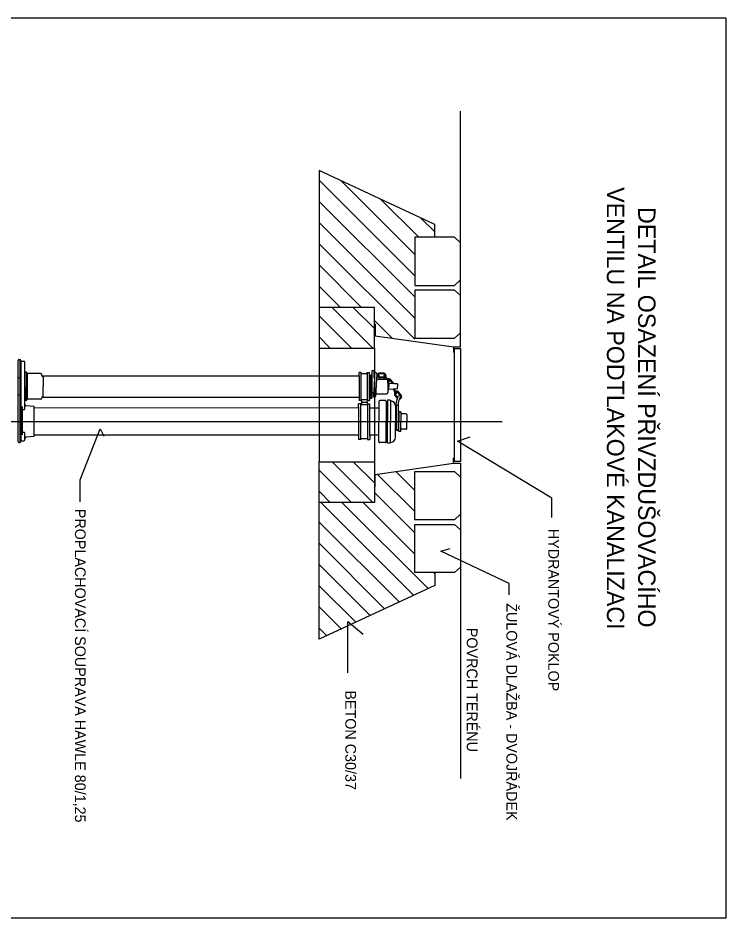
# Model space of a CAD drawing. Extents: x -548894.87 to -548891.9, y -1151272.48 to -1151270.38.
# Drawn here: x -548893.547 to -548891.896, y -1151272.484 to -1151270.384 of the extents above; entities that cross this region are included whole.
import ezdxf

# ---------------------------------------------------------------- set-up
doc = ezdxf.new("R2010")
doc.units = 0
doc.layers.add('Implicitní', color=7, linetype='Continuous')
doc.layers.add('Vrstva 2', color=7, linetype='Continuous')

msp = doc.modelspace()

# ---------------------------------------------------------------- linework, layer by layer
at = {"layer": 'Implicitní'}
for p, q in [((-548893.5465, -1151271.2988), (-548893.5465, -1151271.1823)), ((-548893.545, -1151271.1808), (-548893.5425, -1151271.1808)), ((-548893.5402, -1151271.1848), (-548893.5425, -1151271.1808)), ((-548893.5425, -1151271.3258), (-548893.5425, -1151271.1808)), ((-548893.5402, -1151271.1848), (-548893.5335, -1151271.1848)), ((-548893.5402, -1151271.3258), (-548893.5402, -1151271.1848)), ((-548893.5315, -1151271.285), (-548893.5315, -1151271.1868)), ((-548893.5275, -1151271.2108), (-548893.5315, -1151271.2108)), ((-548893.5315, -1151271.2438), (-548893.5315, -1151271.2108)), ((-548893.5275, -1151271.2768), (-548893.5275, -1151271.2108)), ((-548893.5275, -1151271.2108), (-548893.5257, -1151271.2138)), ((-548893.5257, -1151271.2138), (-548893.5257, -1151271.2738)), ((-548893.4945, -1151271.2138), (-548893.5257, -1151271.2138)), ((-548893.4915, -1151271.2173), (-548893.4915, -1151271.2168)), ((-548893.4887, -1151271.2188), (-548893.4069, -1151271.2188)), ((-548893.4887, -1151271.2188), (-548893.4887, -1151271.2438)), ((-548893.4069, -1151271.2188), (-548892.7516, -1151271.2188)), ((-548892.7466, -1151271.2113), (-548892.7516, -1151271.2113)), ((-548892.7516, -1151271.2188), (-548892.7516, -1151271.2113)), ((-548892.7516, -1151271.2188), (-548892.7516, -1151271.2763)), ((-548892.7466, -1151271.2743), (-548892.7466, -1151271.2113)), ((-548892.7466, -1151271.2133), (-548892.7326, -1151271.2133)), ((-548892.7326, -1151271.2133), (-548892.7326, -1151271.2113)), ((-548892.7326, -1151271.2113), (-548892.7276, -1151271.2113)), ((-548892.7326, -1151271.2133), (-548892.7326, -1151271.2763)), ((-548892.7276, -1151271.2763), (-548892.7276, -1151271.2113)), ((-548892.7276, -1151271.2188), (-548892.7246, -1151271.2188)), ((-548892.7246, -1151271.2668), (-548892.7246, -1151271.2168)), ((-548892.7246, -1151271.2168), (-548892.7216, -1151271.2168)), ((-548892.7216, -1151271.258), (-548892.7216, -1151271.2168)), ((-548892.7211, -1151271.2063), (-548892.7176, -1151271.2063)), ((-548892.7211, -1151271.258), (-548892.7211, -1151271.2063)), ((-548892.7161, -1151271.2248), (-548892.7161, -1151271.2078)), ((-548892.7155, -1151271.2162), (-548892.7161, -1151271.2161)), ((-548892.7157, -1151271.2183), (-548892.7161, -1151271.2182)), ((-548892.7154, -1151271.214), (-548892.716, -1151271.2248)), ((-548892.7104, -1151271.2142), (-548892.7119, -1151271.2404)), ((-548892.7061, -1151271.2191), (-548892.7107, -1151271.2187)), ((-548892.7058, -1151271.217), (-548892.7106, -1151271.2166)), ((-548892.6941, -1151271.2149), (-548892.7037, -1151271.2147)), ((-548892.694, -1151271.2128), (-548892.7036, -1151271.2126)), ((-548892.6816, -1151271.2314), (-548892.6921, -1151271.2184)), ((-548893.5425, -1151271.2238), (-548893.5465, -1151271.2238)), ((-548893.5465, -1151271.3258), (-548893.5465, -1151271.2258)), ((-548893.5402, -1151271.2258), (-548893.5425, -1151271.2258)), ((-548892.716, -1151271.2248), (-548892.7183, -1151271.2664)), ((-548892.7111, -1151271.2268), (-548892.6876, -1151271.2268)), ((-548892.6943, -1151271.224), (-548892.7039, -1151271.2238)), ((-548892.6943, -1151271.2219), (-548892.7038, -1151271.2217)), ((-548892.688, -1151271.2268), (-548892.6938, -1151271.2197)), ((-548892.6846, -1151271.2363), (-548892.6846, -1151271.2298)), ((-548892.6846, -1151271.2298), (-548892.6846, -1151271.2578)), ((-548892.6832, -1151271.2327), (-548892.6846, -1151271.231)), ((-548892.6822, -1151271.2369), (-548892.6846, -1151271.234)), ((-548892.6846, -1151271.2368), (-548892.682, -1151271.2368)), ((-548892.6687, -1151271.2375), (-548892.682, -1151271.2368)), ((-548892.682, -1151271.2368), (-548892.682, -1151271.2438)), ((-548892.6729, -1151271.2374), (-548892.6793, -1151271.2294)), ((-548892.6701, -1151271.2376), (-548892.6776, -1151271.2281)), ((-548892.662, -1151271.2378), (-548892.6687, -1151271.2375)), ((-548892.662, -1151271.2378), (-548892.662, -1151271.2438)), ((-548893.5315, -1151271.2438), (-548893.5315, -1151271.2768)), ((-548893.4887, -1151271.2688), (-548893.4887, -1151271.2438)), ((-548892.7216, -1151271.258), (-548892.7216, -1151271.2708)), ((-548892.7216, -1151271.258), (-548892.7178, -1151271.258)), ((-548892.7119, -1151271.2404), (-548892.7133, -1151271.2667)), ((-548892.7126, -1151271.2588), (-548892.7126, -1151271.2608)), ((-548892.7126, -1151271.2608), (-548892.6876, -1151271.2608)), ((-548892.6846, -1151271.2508), (-548892.682, -1151271.2508)), ((-548892.682, -1151271.2508), (-548892.682, -1151271.2438)), ((-548892.662, -1151271.2497), (-548892.682, -1151271.2508)), ((-548892.666, -1151271.2595), (-548892.6714, -1151271.2502)), ((-548892.6642, -1151271.2585), (-548892.669, -1151271.2501)), ((-548892.662, -1151271.2497), (-548892.662, -1151271.2438)), ((-548892.6551, -1151271.2655), (-548892.661, -1151271.258)), ((-548892.6534, -1151271.2642), (-548892.6594, -1151271.2567)), ((-548893.5425, -1151271.2638), (-548893.5465, -1151271.2638)), ((-548893.5402, -1151271.2618), (-548893.5425, -1151271.2618)), ((-548893.5275, -1151271.2768), (-548893.5315, -1151271.2768)), ((-548893.5275, -1151271.2768), (-548893.5257, -1151271.2738)), ((-548893.4945, -1151271.2738), (-548893.5257, -1151271.2738)), ((-548893.4915, -1151271.2703), (-548893.4915, -1151271.2708)), ((-548893.4887, -1151271.2688), (-548893.4069, -1151271.2688)), ((-548893.4069, -1151271.2688), (-548892.7516, -1151271.2688)), ((-548892.7466, -1151271.2763), (-548892.7516, -1151271.2763)), ((-548892.7466, -1151271.2743), (-548892.7466, -1151271.2763)), ((-548892.7466, -1151271.2743), (-548892.7326, -1151271.2743)), ((-548892.7461, -1151271.2743), (-548892.7461, -1151271.2792)), ((-548892.7451, -1151271.2802), (-548892.7461, -1151271.2792)), ((-548892.7451, -1151271.2802), (-548892.7461, -1151271.2812)), ((-548892.7461, -1151271.2812), (-548892.7461, -1151271.2862)), ((-548892.7451, -1151271.2802), (-548892.7436, -1151271.2802)), ((-548892.7436, -1151271.2802), (-548892.7341, -1151271.2802)), ((-548892.7341, -1151271.2802), (-548892.7331, -1151271.2792)), ((-548892.7341, -1151271.2802), (-548892.7331, -1151271.2812)), ((-548892.7331, -1151271.2743), (-548892.7331, -1151271.2792)), ((-548892.7331, -1151271.2812), (-548892.7331, -1151271.2862)), ((-548892.7326, -1151271.2763), (-548892.7276, -1151271.2763)), ((-548892.7276, -1151271.2688), (-548892.7246, -1151271.2688)), ((-548892.7276, -1151271.2688), (-548892.7276, -1151271.2763)), ((-548892.7246, -1151271.2668), (-548892.7246, -1151271.2708)), ((-548892.7246, -1151271.2708), (-548892.7216, -1151271.2708)), ((-548892.7056, -1151271.2788), (-548892.7056, -1151271.3258)), ((-548892.6901, -1151271.2768), (-548892.7036, -1151271.2768)), ((-548892.6881, -1151271.2788), (-548892.6881, -1151271.3258)), ((-548892.6856, -1151271.2763), (-548892.6856, -1151271.3258)), ((-548892.6791, -1151271.2758), (-548892.6851, -1151271.2758)), ((-548892.6786, -1151271.2763), (-548892.6786, -1151271.3258)), ((-548892.6619, -1151271.2716), (-548892.6682, -1151271.2637)), ((-548892.6609, -1151271.2694), (-548892.6665, -1151271.2624)), ((-548893.5402, -1151271.2988), (-548893.5402, -1151271.2978)), ((-548893.5365, -1151271.3566), (-548893.5365, -1151271.2903)), ((-548893.5365, -1151271.2978), (-548893.5335, -1151271.2978)), ((-548893.5315, -1151271.2958), (-548893.5315, -1151271.285)), ((-548893.5095, -1151271.2906), (-548893.5278, -1151271.289)), ((-548893.5095, -1151271.3541), (-548893.5095, -1151271.2906)), ((-548892.7528, -1151271.2941), (-548893.5095, -1151271.2937)), ((-548892.7473, -1151271.284), (-548892.7528, -1151271.284)), ((-548892.7528, -1151271.2923), (-548892.7528, -1151271.284)), ((-548892.7528, -1151271.2923), (-548892.7528, -1151271.3675)), ((-548892.7473, -1151271.3653), (-548892.7473, -1151271.284)), ((-548892.7473, -1151271.2862), (-548892.7319, -1151271.2862)), ((-548892.7319, -1151271.284), (-548892.7264, -1151271.284)), ((-548892.7319, -1151271.2862), (-548892.7319, -1151271.284)), ((-548892.7319, -1151271.2862), (-548892.7319, -1151271.3675)), ((-548892.7264, -1151271.3593), (-548892.7264, -1151271.284)), ((-548892.7055, -1151271.2941), (-548892.7264, -1151271.2941)), ((-548892.7056, -1151271.2923), (-548892.7056, -1151271.296)), ((-548892.7056, -1151271.2923), (-548892.7056, -1151271.296)), ((-548892.6856, -1151271.2968), (-548892.6881, -1151271.2968)), ((-548892.6666, -1151271.2893), (-548892.6666, -1151271.3258)), ((-548892.6601, -1151271.2882), (-548892.6651, -1151271.288)), ((-548892.6651, -1151271.288), (-548892.6651, -1151271.3438)), ((-548892.6601, -1151271.2881), (-548892.6601, -1151271.3438)), ((-548892.6546, -1151271.3028), (-548892.6586, -1151271.3028)), ((-548892.6586, -1151271.3028), (-548892.6586, -1151271.3258)), ((-548892.6546, -1151271.3028), (-548892.6546, -1151271.3258)), ((-548893.5465, -1151271.3258), (-548893.5465, -1151271.3118)), ((-548892.6651, -1151271.3098), (-548892.6666, -1151271.3098)), ((-548892.6586, -1151271.3098), (-548892.6601, -1151271.3098)), ((-548892.6421, -1151271.3078), (-548892.6531, -1151271.3078)), ((-548892.6406, -1151271.3093), (-548892.6406, -1151271.3258)), ((-548893.5465, -1151271.3728), (-548893.5465, -1151271.3258)), ((-548893.5425, -1151271.3743), (-548893.5425, -1151271.3258)), ((-548893.5402, -1151271.3703), (-548893.5402, -1151271.3258)), ((-548892.7056, -1151271.3728), (-548892.7056, -1151271.3258)), ((-548892.7056, -1151271.3556), (-548892.7056, -1151271.3258)), ((-548892.6881, -1151271.3728), (-548892.6881, -1151271.3258)), ((-548892.6856, -1151271.3753), (-548892.6856, -1151271.3258)), ((-548892.6786, -1151271.3753), (-548892.6786, -1151271.3258)), ((-548892.6666, -1151271.3623), (-548892.6666, -1151271.3258)), ((-548892.6651, -1151271.3418), (-548892.6666, -1151271.3418)), ((-548892.6586, -1151271.3418), (-548892.6601, -1151271.3418)), ((-548892.6586, -1151271.3488), (-548892.6586, -1151271.3258)), ((-548892.6546, -1151271.3488), (-548892.6546, -1151271.3258)), ((-548892.6421, -1151271.3438), (-548892.6531, -1151271.3438)), ((-548892.6406, -1151271.3423), (-548892.6406, -1151271.3258)), ((-548893.5365, -1151271.3503), (-548893.5335, -1151271.3503)), ((-548893.5315, -1151271.3683), (-548893.5315, -1151271.3523)), ((-548893.5095, -1151271.3609), (-548893.5278, -1151271.3625)), ((-548893.5095, -1151271.3609), (-548893.5095, -1151271.3541)), ((-548893.5095, -1151271.3575), (-548893.5095, -1151271.3556)), ((-548892.7528, -1151271.3575), (-548893.5095, -1151271.3575)), ((-548892.7473, -1151271.3653), (-548892.7473, -1151271.3675)), ((-548892.7473, -1151271.3653), (-548892.7319, -1151271.3653)), ((-548892.7056, -1151271.3575), (-548892.7264, -1151271.3575)), ((-548892.7264, -1151271.3593), (-548892.7264, -1151271.3675)), ((-548892.7056, -1151271.3593), (-548892.7056, -1151271.3556)), ((-548892.7056, -1151271.3593), (-548892.7056, -1151271.3556)), ((-548892.6856, -1151271.3548), (-548892.6881, -1151271.3548)), ((-548892.6546, -1151271.3488), (-548892.6586, -1151271.3488)), ((-548893.545, -1151271.3743), (-548893.5425, -1151271.3743)), ((-548893.5425, -1151271.3743), (-548893.5402, -1151271.3703)), ((-548893.5402, -1151271.3703), (-548893.5335, -1151271.3703)), ((-548892.7473, -1151271.3675), (-548892.7528, -1151271.3675)), ((-548892.7319, -1151271.3675), (-548892.7264, -1151271.3675)), ((-548892.6901, -1151271.3748), (-548892.7036, -1151271.3748)), ((-548892.6791, -1151271.3758), (-548892.6851, -1151271.3758))]:
    msp.add_line(p, q, dxfattribs=at)
for centre, radius, start, end in [((-548893.545, -1151271.1823), 0.0015, 89.9984, 179.9985), ((-548893.5335, -1151271.1868), 0.002, 359.9984, 89.9984), ((-548893.4945, -1151271.2168), 0.003, 359.9984, 89.9984), ((-548893.4875, -1151271.2173), 0.004, 179.9984, 251.9277), ((-548892.7176, -1151271.2078), 0.0015, 359.9984, 89.9984), ((-548892.7129, -1151271.2141), 0.0025, 357.4051, 177.4051), ((-548892.7037, -1151271.2182), 0.0056, 186.5665, 268.4824), ((-548892.7037, -1151271.2182), 0.0056, 88.4824, 165.247), ((-548892.7037, -1151271.2182), 0.0035, 88.4824, 159.2748), ((-548892.7059, -1151271.2181), 0.00105, 259.7582, 86.2847), ((-548892.6942, -1151271.2184), 0.0035, 336.4446, 88.4824), ((-548892.6942, -1151271.2184), 0.0056, 325.741, 88.4824), ((-548892.6929, -1151271.219), 0.00105, 38.9488, 218.9488), ((-548892.7037, -1151271.2182), 0.0035, 194.126, 268.4824), ((-548892.6942, -1151271.2184), 0.0035, 268.4824, 301.0036), ((-548892.6942, -1151271.2184), 0.0056, 268.4824, 304.0115), ((-548892.6876, -1151271.2298), 0.003, 359.9984, 89.9984), ((-548892.682, -1151271.2316), 0.0056, 38.4824, 124.1839), ((-548892.682, -1151271.2316), 0.0035, 38.4824, 121.2809), ((-548892.6824, -1151271.2321), 0.00105, 213.7582, 40.2847), ((-548892.6876, -1151271.2578), 0.003, 269.9984, 359.9984), ((-548892.6638, -1151271.2602), 0.0056, 136.5665, 218.4824), ((-548892.6638, -1151271.2602), 0.0035, 147.1436, 218.4824), ((-548892.6638, -1151271.2602), 0.0056, 38.4824, 114.8437), ((-548892.6651, -1151271.259), 0.00105, 209.996, 30.0008), ((-548892.6638, -1151271.2602), 0.0035, 38.4824, 111.7333), ((-548893.4945, -1151271.2708), 0.003, 269.9984, 359.9984), ((-548893.4875, -1151271.2703), 0.004, 108.069, 179.9984), ((-548892.7158, -1151271.2665), 0.0025, 176.8967, 356.8967), ((-548892.7036, -1151271.2788), 0.002, 89.9984, 179.9984), ((-548892.6901, -1151271.2788), 0.002, 359.9984, 89.9984), ((-548892.6851, -1151271.2763), 0.0005, 89.9984, 179.9984), ((-548892.6791, -1151271.2763), 0.0005, 359.9984, 89.9984), ((-548892.6776, -1151271.2763), 0.001, 179.9984, 265.5867), ((-548892.6786, -1151271.2893), 0.012, 359.9984, 85.5867), ((-548892.6575, -1151271.2679), 0.0025, 334.6366, 154.6366), ((-548892.6578, -1151271.2677), 0.0056, 276.4406, 38.4824), ((-548892.6578, -1151271.2677), 0.0035, 300.4633, 38.4824), ((-548893.5335, -1151271.2958), 0.002, 269.9984, 359.9984), ((-548893.5275, -1151271.285), 0.004, 179.9984, 264.9984), ((-548892.6531, -1151271.3063), 0.0015, 179.9984, 269.9984), ((-548892.6421, -1151271.3093), 0.0015, 359.9984, 89.9984), ((-548892.6626, -1151271.3438), 0.0025, 179.9984, 359.9984), ((-548892.6531, -1151271.3453), 0.0015, 89.9984, 179.9984), ((-548892.6421, -1151271.3423), 0.0015, 269.9984, 359.9984), ((-548893.5335, -1151271.3523), 0.002, 359.9984, 89.9984), ((-548893.5275, -1151271.3665), 0.004, 94.9984, 179.9984), ((-548892.6786, -1151271.3623), 0.012, 274.4101, 359.9984), ((-548893.545, -1151271.3728), 0.0015, 179.9985, 269.9984), ((-548893.5335, -1151271.3683), 0.002, 269.9984, 359.9984), ((-548892.7036, -1151271.3728), 0.002, 179.9984, 269.9984), ((-548892.6901, -1151271.3728), 0.002, 269.9984, 359.9984), ((-548892.6851, -1151271.3753), 0.0005, 179.9984, 269.9984), ((-548892.6791, -1151271.3753), 0.0005, 269.9984, 359.9984), ((-548892.6776, -1151271.3752), 0.001, 94.4101, 179.9984)]:
    msp.add_arc(centre, radius, start, end, dxfattribs=at)
for points in [[(-548892.6651, -1151271.288), (-548892.6649, -1151271.2842), (-548892.6645, -1151271.2768), (-548892.6613, -1151271.2701), (-548892.6597, -1151271.2668)], [(-548892.6601, -1151271.2882), (-548892.66, -1151271.2874), (-548892.6599, -1151271.2857), (-548892.6598, -1151271.2832), (-548892.6595, -1151271.2807), (-548892.659, -1151271.2782), (-548892.6582, -1151271.2758), (-548892.6573, -1151271.2735), (-548892.6563, -1151271.2712), (-548892.6556, -1151271.2697), (-548892.6552, -1151271.2689)]]:
    msp.add_open_spline(points, degree=3, dxfattribs=at)
at = {"layer": 'Vrstva 2'}
for p, q in [((-548891.8958, -1151270.3841), (-548894.8658, -1151270.3841)), ((-548891.8958, -1151270.3841), (-548891.8958, -1151272.4841)), ((-548892.5149, -1151271.1515), (-548892.5149, -1151270.6017)), ((-548892.5753, -1151270.8658), (-548892.8447, -1151270.7402)), ((-548892.8447, -1151270.7402), (-548892.8447, -1151271.0594)), ((-548892.8447, -1151270.7624), (-548892.6217, -1151270.9855)), ((-548892.7937, -1151270.7639), (-548892.6217, -1151270.936)), ((-548892.8447, -1151270.8119), (-548892.6217, -1151271.035)), ((-548892.701, -1151270.8072), (-548892.6124, -1151270.8957)), ((-548892.8447, -1151270.8614), (-548892.6217, -1151271.0845)), ((-548892.6082, -1151270.8504), (-548892.5753, -1151270.8833)), ((-548892.5753, -1151270.8957), (-548892.5753, -1151270.8658)), ((-548892.8447, -1151270.9109), (-548892.6219, -1151271.1337)), ((-548892.8447, -1151270.9604), (-548892.7457, -1151271.0594)), ((-548892.8447, -1151271.0099), (-548892.7952, -1151271.0594)), ((-548892.8147, -1151271.0594), (-548892.7197, -1151271.1544)), ((-548892.7652, -1151271.0594), (-548892.7158, -1151271.1089)), ((-548892.8447, -1151271.0789), (-548892.7692, -1151271.1544)), ((-548892.7148, -1151271.0903), (-548892.6741, -1151271.131)), ((-548892.7138, -1151271.0979), (-548892.7138, -1151271.1253)), ((-548892.8447, -1151271.1284), (-548892.8187, -1151271.1544)), ((-548892.7138, -1151271.1253), (-548892.5313, -1151271.1515)), ((-548892.8447, -1151271.1544), (-548892.8447, -1151271.4194)), ((-548892.7158, -1151271.1544), (-548892.7158, -1151271.4194)), ((-548892.5313, -1151271.1515), (-548892.5149, -1151271.1515)), ((-548892.5313, -1151271.1515), (-548892.5313, -1151271.1642)), ((-548893.7084, -1151271.3258), (-548892.4181, -1151271.3258)), ((-548892.8147, -1151271.4194), (-548892.7197, -1151271.5144)), ((-548892.7652, -1151271.4194), (-548892.7158, -1151271.4689)), ((-548892.7138, -1151271.4491), (-548892.5313, -1151271.4229)), ((-548892.5313, -1151271.4229), (-548892.5313, -1151271.4102)), ((-548892.5313, -1151271.4229), (-548892.5149, -1151271.4229)), ((-548892.5149, -1151271.4229), (-548892.5149, -1151272.1586)), ((-548892.8447, -1151271.4389), (-548892.7692, -1151271.5144)), ((-548892.7138, -1151271.4782), (-548892.7138, -1151271.4491)), ((-548892.7091, -1151271.4484), (-548892.6217, -1151271.5358)), ((-548892.6658, -1151271.4422), (-548892.6217, -1151271.4863)), ((-548892.8447, -1151271.4884), (-548892.8187, -1151271.5144)), ((-548892.7151, -1151271.4919), (-548892.6217, -1151271.5853)), ((-548892.8447, -1151271.8337), (-548892.8447, -1151271.5144)), ((-548892.8411, -1151271.5144), (-548892.6245, -1151271.731)), ((-548892.7916, -1151271.5144), (-548892.5907, -1151271.7153)), ((-548892.7421, -1151271.5144), (-548892.6217, -1151271.6348)), ((-548892.8447, -1151271.5603), (-548892.6582, -1151271.7467)), ((-548892.8447, -1151271.6098), (-548892.692, -1151271.7625)), ((-548892.8447, -1151271.6593), (-548892.7258, -1151271.7782)), ((-548892.5784, -1151271.6781), (-548892.5753, -1151271.6812)), ((-548892.5753, -1151271.6781), (-548892.5753, -1151271.7081)), ((-548892.5753, -1151271.7081), (-548892.8447, -1151271.8337)), ((-548892.8447, -1151271.7087), (-548892.7595, -1151271.7939)), ((-548892.8447, -1151271.7582), (-548892.7933, -1151271.8097)), ((-548892.8447, -1151271.8077), (-548892.827, -1151271.8254)), ((-548891.8958, -1151272.4841), (-548894.8658, -1151272.4841))]:
    msp.add_line(p, q, dxfattribs=at)
for points in [[(-548892.6217, -1151270.8957), (-548892.6217, -1151271.0081), (-548892.6077, -1151271.0081), (-548892.5289, -1151271.0081), (-548892.5149, -1151270.9953), (-548892.5149, -1151270.9086), (-548892.5289, -1151270.8957)], [(-548892.6217, -1151271.0191), (-548892.6217, -1151271.1314), (-548892.6077, -1151271.1314), (-548892.5289, -1151271.1314), (-548892.5149, -1151271.1186), (-548892.5149, -1151271.0319), (-548892.5289, -1151271.0191)], [(-548892.7158, -1151271.1544), (-548892.7158, -1151271.0594), (-548892.8447, -1151271.0594), (-548892.8447, -1151271.1544)], [(-548892.5152, -1151271.155), (-548892.5152, -1151271.4189), (-548892.5293, -1151271.4189), (-548892.5293, -1151271.155)], [(-548892.7158, -1151271.4194), (-548892.7158, -1151271.5144), (-548892.8447, -1151271.5144), (-548892.8447, -1151271.4194)], [(-548892.6217, -1151271.5548), (-548892.6217, -1151271.4424), (-548892.6077, -1151271.4424), (-548892.5289, -1151271.4424), (-548892.5149, -1151271.4552), (-548892.5149, -1151271.5419), (-548892.5289, -1151271.5548)], [(-548892.6217, -1151271.6781), (-548892.6217, -1151271.5657), (-548892.6077, -1151271.5657), (-548892.5289, -1151271.5657), (-548892.5149, -1151271.5785), (-548892.5149, -1151271.6653), (-548892.5289, -1151271.6781)]]:
    msp.add_lwpolyline(points, close=True, dxfattribs=at)
for points in [[(-548893.4024, -1151271.5132), (-548893.4024, -1151271.4613), (-548893.3552, -1151271.3425), (-548893.347, -1151271.3596)], [(-548892.302, -1151271.5494), (-548892.302, -1151271.5044), (-548892.5224, -1151271.3712), (-548892.4924, -1151271.3617)], [(-548892.4015, -1151271.7297), (-548892.4015, -1151271.7032), (-548892.5606, -1151271.6284), (-548892.5388, -1151271.6222)], [(-548892.7776, -1151271.912), (-548892.7776, -1151271.792), (-548892.7423, -1151271.822)]]:
    msp.add_lwpolyline(points, dxfattribs=at)

# ---------------------------------------------------------------- texts
for s, height, p in [('VENTILU NA PODTLAKOVÉ KANALIZACI', 0.040501, (-548892.1736, -1151270.7788)), ('DETAIL OSAZENÍ PŘIVZDUŠOVACÍHO ', 0.040501, (-548892.1007, -1151270.8252)), ('PROPLACHOVACÍ SOUPRAVA HAWLE 80/1,25', 0.024999, (-548893.4144, -1151271.5293)), ('HYDRANTOVÝ POKLOP', 0.024999, (-548892.3103, -1151271.576)), ('ŽULOVÁ DLAŽBA - DVOJŘÁDEK', 0.024999, (-548892.408, -1151271.7496)), ('POVRCH TERÉNU', 0.024999, (-548892.5004, -1151271.807)), ('BETON C30/37', 0.024999, (-548892.7838, -1151271.953))]:
    msp.add_text(s, height=height, rotation=270, dxfattribs=at).set_placement(p)

doc.saveas('drawing.dxf')
